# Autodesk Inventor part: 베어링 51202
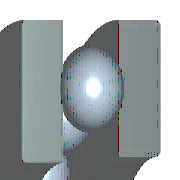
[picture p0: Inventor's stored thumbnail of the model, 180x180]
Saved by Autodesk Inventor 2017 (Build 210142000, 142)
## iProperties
Created: 2012-02
Part Number: 베어링 51202
Material: 강철, 연강
Description: 롤링 베어링 - 플랫 뒷면이 있는 스러스트 볼 베어링
Document SubType Name: Modeling
Standard: KS B 2022
Designer: mduedu
Standards Organization: KS
Language: ko-KR
Size Designation: 51202 - 15 x 32 x 12
Categories: <MemberInstance><Categories><Category DisplayName="샤프트 부품" InternalName="7f7aeb1f-a693-4053-b835-cee3144e0d98" Mnemonic="SHFT"><Category DisplayName="베어링" Inter
Density: 1 g/cm^3
Appearance: 진녹색
IsCustomPart: 1
Author: mduedu
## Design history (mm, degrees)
sketch "스케치1" dims "d3" = 5.28 (= 0.44 x KB)
  geometry: L1 (6, 9.61)-(6, 14.89); L2 (8.64, 12.25)-(3.36, 12.25); L3 (3.6, 16)-(0, 16); L4 (3.6, 7.5)-(0, 7.5); L5 (8.4, 13.35)-(8.4, 16); L6 (8.4, 16)-(12, 16); L7 (12, 16)-(12, 8.5); L8 (12, 8.5)-(8.4, 8.5); L9 (8.4, 8.5)-(8.4, 11.15); L10 (3.6, 16)-(3.6, 13.35); L11 (3.6, 11.15)-(3.6, 7.5); L12 (-1.8, 0)-(10.8, 0) reference; L13 (0, -0.022)-(0, 5.522) reference; 1 further point
  constraints: 22 end point, 5 perpendicular, 2 equal length, 2 midpoint, 2 parallel, 2 point on line, 1 collinear, 10 other
  dimensions: "d8" = 4.8 diameter of L11 L1 (= 0.4 x KB); "d11" = 15 diameter of L4 L12 (= WD); "d12" = 17 diameter of L8 L12 (= KAD1); "d13" = 32 diameter of L3 L12 (= KID1); "d14" = 32 diameter of L6 L12 (= BD); "d15" = 24.5 diameter of point (6, 12.25) L12 (= 0.5 x KID1 + 0.5 x KAD1); "d16" = 6 distance from line of point (6, 12.25) L13 (= 0.5 x KB); "d18" = 12 distance between parallel lines of L7 L13 (= KB)
revolve "본체" stored, may be unused: angle "d9" = 90 deg
revolve "볼" stored, may be unused: angle "d10" = 90 deg
pattern_circular "IDS_ARRAYBALL[SIMPL:T]" dims angle "d2" = 360 deg
body "Solid1"
fillet "모깎기1" dims "d4" = 0.6 (= KRS)
fillet "모깎기2" dims "d5" = 0.6 (= KRS)
other parameters: "WD" = 15 [user parameter; used in 2 equation terms], "KAD1" = 17 [user parameter; used in 3 equation terms], "KID1" = 32 [user parameter; used in 3 equation terms], "BD" = 32 [user parameter; used in 2 equation terms], "KB" = 12 [user parameter; used in 6 equation terms], "KRS" = 0.6 [user parameter; used in 2 equation terms], "d0" = 2.4 (= 0.2 x KB), "d6" = 0, "d7" = 0, "d19" = 0, "d41" = 0, "d42" = 0, "WR" = 7.5 (= 0.5 x WD) [user parameter], "BC" = 1.65e+07 [user parameter], "BBA" = 90 deg [user parameter], "BC0" = 2.7e+07 [user parameter], "BR" = 16 (= 0.5 x BD) [user parameter]
